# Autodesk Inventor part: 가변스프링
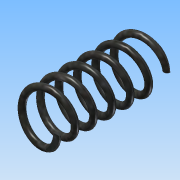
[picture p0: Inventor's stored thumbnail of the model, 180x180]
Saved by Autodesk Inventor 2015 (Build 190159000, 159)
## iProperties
Created: 2020-02
Part Number: 가변스프링
Material: 강철
Document SubType Name: Modeling
Designer: user
Density: 7.85 g/cm^3
Appearance: 플레이트
Mass: 6.42947 g
Surface Area: 16.622 cm^2
Volume: 0.81904 cm^3
Author: user
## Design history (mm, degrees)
sketch "스케치1"
  geometry: L1 (0, 0)-(7, 0); L2 (7, 0)-(7, 35.5); L3 (7, 35.5)-(0, 35.5); L4 (0, 35.5)-(0, 0); C1 r 1 at (7, 0)
  constraints: 8 end point, 2 parallel, 1 centre point, 1 coincident, 1 horizontal, 1 perpendicular
  dimensions: "d0" = 7 distance of L1.start L1.end; "d1" = 2 diameter of C1; "d2" = 35.5 distance of L1.end L2.end (derived)
feature "코일1" sketch "스케치1" pitch "d3" = 10; turns "d5" = 6; dims "d4" = 35.5 (= d2), "d6" = 0, angle "d7" = 90 deg, angle "d8" = 90 deg, "d9" = 0, "d10" = 0
node "작업 평면1"
feature "분할1"
feature "분할2"
node "솔리드1"
